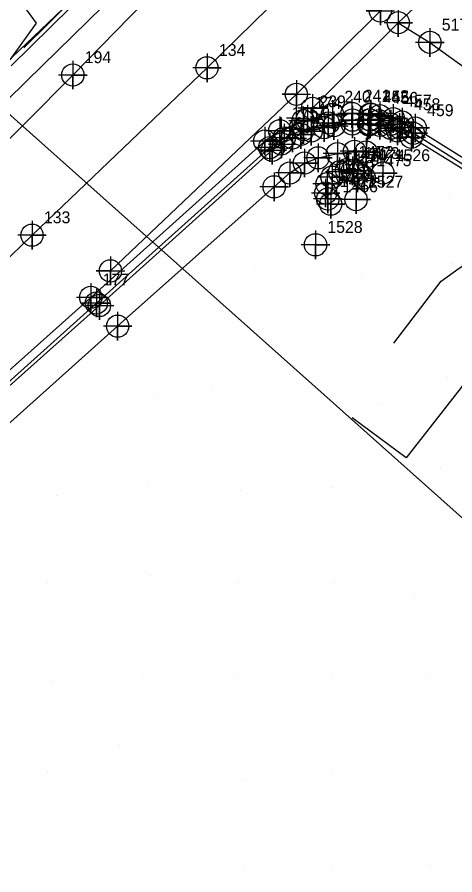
# Model space of a CAD drawing. Extents: x 1497074 to 1501343, y 481943 to 486114.
# Drawn here: x 1498357.2 to 1498449.4, y 484461 to 484641.5 of the extents above; entities that cross this region are included whole.
import ezdxf

# ---------------------------------------------------------------- set-up
doc = ezdxf.new("R2010")
doc.units = 0
for name, color, linetype in [('Exist Building Deck Patio Cogo Number', 7, 'Continuous'), ('Exist Building Deck Patio Cogo Point CELL', 7, 'Continuous'), ('Exist DTM Breakline', 7, 'Continuous'), ('Exist DTM Breakline Cogo Point CELL', 7, 'Continuous'), ('Exist DTM Crownline', 7, 'Continuous'), ('Exist DTM Crownline Cogo Number', 7, 'Continuous'), ('Exist DTM Crownline Cogo Point CELL', 7, 'Continuous'), ('Exist DTM Drainline', 7, 'Continuous'), ('Exist DTM Drainline Cogo Point CELL', 7, 'Continuous'), ('Exist DTM Regular Point CELL', 7, 'Continuous'), ('Exist DTM Regular Point Cogo Number', 7, 'Continuous'), ('Exist Guardrail', 7, 'Continuous'), ('Exist Roads Curbs', 7, 'Continuous'), ('Exist Roads Curbs Cogo Point CELL', 7, 'Continuous'), ('Exist Roads EOP', 7, 'Continuous'), ('Exist Roads EOP Cogo Number', 7, 'Continuous'), ('Exist Roads EOP Cogo Point CELL', 7, 'Continuous'), ('Exist Roads EOP Other', 7, 'Continuous'), ('Exist Roads EOP Other Cogo Point CELL', 7, 'Continuous'), ('Exist Roads EOT', 7, 'Continuous'), ('Exist Roads EOT Cogo Point CELL', 7, 'Continuous'), ('PH Exist DTM Boundary', 7, 'Continuous'), ('PH Exist DTM Breakline', 7, 'Continuous'), ('PH Exist DTM Obscure Area', 7, 'Continuous'), ('PH Exist DTM Point', 7, 'Continuous')]:
    doc.layers.add(name, color=color, linetype=linetype)

msp = doc.modelspace()

# ---------------------------------------------------------------- linework, layer by layer
at = {"layer": 'Exist Building Deck Patio Cogo Point CELL'}
for points in [[(1498425.08, 484611.93), (1498425.08, 484605.93), (1498425.08, 484608.93), (1498428.08, 484608.93), (1498422.08, 484608.93)], [(1498426.54, 484612.37), (1498426.54, 484606.37), (1498426.54, 484609.37), (1498429.54, 484609.37), (1498423.54, 484609.37)], [(1498427.76, 484612.14), (1498427.76, 484606.14), (1498427.76, 484609.14), (1498430.76, 484609.14), (1498424.76, 484609.14)], [(1498428.9, 484611.6), (1498428.9, 484605.6), (1498428.9, 484608.6), (1498431.9, 484608.6), (1498425.9, 484608.6)], [(1498422.44, 484609.42), (1498422.44, 484603.42), (1498422.44, 484606.42), (1498425.44, 484606.42), (1498419.44, 484606.42)], [(1498423.48, 484610.81), (1498423.48, 484604.81), (1498423.48, 484607.81), (1498426.48, 484607.81), (1498420.48, 484607.81)], [(1498430.28, 484610.62), (1498430.28, 484604.62), (1498430.28, 484607.62), (1498433.28, 484607.62), (1498427.28, 484607.62)], [(1498422.13, 484607.48), (1498422.13, 484601.48), (1498422.13, 484604.48), (1498425.13, 484604.48), (1498419.13, 484604.48)], [(1498422.59, 484606.22), (1498422.59, 484600.22), (1498422.59, 484603.22), (1498425.59, 484603.22), (1498419.59, 484603.22)], [(1498423.21, 484605.13), (1498423.21, 484599.13), (1498423.21, 484602.13), (1498426.21, 484602.13), (1498420.21, 484602.13)]]:
    msp.add_lwpolyline(points, dxfattribs=at)
for centre in [(1498425.08, 484608.93), (1498426.54, 484609.37), (1498427.76, 484609.14), (1498423.48, 484607.81), (1498428.9, 484608.6), (1498430.28, 484607.62), (1498422.44, 484606.42), (1498422.13, 484604.48), (1498422.59, 484603.22), (1498423.21, 484602.13)]:
    msp.add_circle(centre, 2.34, dxfattribs=at)
at = {"layer": 'Exist DTM Breakline'}
for points in [[(1498231.12, 484516.09), (1498254.57, 484537.6), (1498277.62, 484558.98), (1498300.74, 484581.31), (1498327.42, 484605.51), (1498348.5, 484625.92), (1498369.75, 484646.08), (1498390.54, 484667.65), (1498409.77, 484686.85)], [(1498467.53, 484668.57), (1498437.44, 484640.31), (1498419.38, 484622.3)]]:
    msp.add_lwpolyline(points, dxfattribs=at)
at = {"layer": 'Exist DTM Breakline Cogo Point CELL'}
for points in [[(1498437.44, 484643.31), (1498437.44, 484637.31), (1498437.44, 484640.31), (1498440.44, 484640.31), (1498434.44, 484640.31)], [(1498419.38, 484625.3), (1498419.38, 484619.3), (1498419.38, 484622.3), (1498422.38, 484622.3), (1498416.38, 484622.3)]]:
    msp.add_lwpolyline(points, dxfattribs=at)
for centre in [(1498437.44, 484640.31), (1498419.38, 484622.3)]:
    msp.add_circle(centre, 2.34, dxfattribs=at)
at = {"layer": 'Exist DTM Crownline'}
for points in [[(1498174.51, 484418.76), (1498211.76, 484454.63), (1498248.88, 484490.3), (1498287.28, 484525.89), (1498324.11, 484560.63), (1498360.29, 484595.61), (1498397.16, 484630.83), (1498419.58, 484652.79), (1498435.06, 484667.86), (1498471.56, 484703.24), (1498507.82, 484739.07), (1498544.95, 484775.1), (1498579.44, 484811.19), (1498593.31, 484825.81), (1498614.8, 484848.72), (1498648.9, 484888.1), (1498682.16, 484928.34), (1498714.31, 484969.37), (1498734.43, 484994.62)], [(1498437.44, 484640.31), (1498444.09, 484636.17), (1498465.05, 484621.1), (1498493.07, 484602.59), (1498534.57, 484574.94), (1498575.81, 484549.45), (1498620.08, 484521.62), (1498662.61, 484494.12)]]:
    msp.add_lwpolyline(points, dxfattribs=at)
at = {"layer": 'Exist DTM Crownline Cogo Point CELL'}
for points in [[(1498444.09, 484639.17), (1498444.09, 484633.17), (1498444.09, 484636.17), (1498447.09, 484636.17), (1498441.09, 484636.17)], [(1498397.16, 484633.83), (1498397.16, 484627.83), (1498397.16, 484630.83), (1498400.16, 484630.83), (1498394.16, 484630.83)], [(1498360.29, 484598.61), (1498360.29, 484592.61), (1498360.29, 484595.61), (1498363.29, 484595.61), (1498357.29, 484595.61)]]:
    msp.add_lwpolyline(points, dxfattribs=at)
for centre in [(1498444.09, 484636.17), (1498397.16, 484630.83), (1498360.29, 484595.61)]:
    msp.add_circle(centre, 2.34, dxfattribs=at)
at = {"layer": 'Exist DTM Drainline'}
for points in [[(1498187.75, 484405.46), (1498224.25, 484440.47), (1498261.49, 484476.23), (1498299.56, 484512.89), (1498328.14, 484540.34), (1498373.86, 484581.33), (1498410.37, 484614.04), (1498413.4, 484616.06), (1498417.45, 484617.85), (1498422.69, 484619.19), (1498427.8, 484619.82), (1498431.51, 484619.86)], [(1498456.84, 484606.28), (1498453.09, 484609.22), (1498440.58, 484617.04), (1498437.69, 484618.27), (1498435.85, 484618.97), (1498433.34, 484619.71), (1498431.51, 484619.86)]]:
    msp.add_lwpolyline(points, dxfattribs=at)
at = {"layer": 'Exist DTM Drainline Cogo Point CELL'}
for points in [[(1498422.69, 484622.19), (1498422.69, 484616.19), (1498422.69, 484619.19), (1498425.69, 484619.19), (1498419.69, 484619.19)], [(1498427.8, 484622.82), (1498427.8, 484616.82), (1498427.8, 484619.82), (1498430.8, 484619.82), (1498424.8, 484619.82)], [(1498431.4, 484622.92), (1498431.4, 484616.92), (1498431.4, 484619.92), (1498434.4, 484619.92), (1498428.4, 484619.92)], [(1498431.51, 484622.86), (1498431.51, 484616.86), (1498431.51, 484619.86), (1498434.51, 484619.86), (1498428.51, 484619.86)], [(1498433.34, 484622.71), (1498433.34, 484616.71), (1498433.34, 484619.71), (1498436.34, 484619.71), (1498430.34, 484619.71)], [(1498435.85, 484621.97), (1498435.85, 484615.97), (1498435.85, 484618.97), (1498438.85, 484618.97), (1498432.85, 484618.97)], [(1498417.45, 484620.85), (1498417.45, 484614.85), (1498417.45, 484617.85), (1498420.45, 484617.85), (1498414.45, 484617.85)], [(1498437.69, 484621.27), (1498437.69, 484615.27), (1498437.69, 484618.27), (1498440.69, 484618.27), (1498434.69, 484618.27)], [(1498413.4, 484619.06), (1498413.4, 484613.06), (1498413.4, 484616.06), (1498416.4, 484616.06), (1498410.4, 484616.06)], [(1498440.58, 484620.04), (1498440.58, 484614.04), (1498440.58, 484617.04), (1498443.58, 484617.04), (1498437.58, 484617.04)], [(1498410.37, 484617.04), (1498410.37, 484611.04), (1498410.37, 484614.04), (1498413.37, 484614.04), (1498407.37, 484614.04)], [(1498373.86, 484584.33), (1498373.86, 484578.33), (1498373.86, 484581.33), (1498376.86, 484581.33), (1498370.86, 484581.33)]]:
    msp.add_lwpolyline(points, dxfattribs=at)
for centre in [(1498427.8, 484619.82), (1498431.4, 484619.92), (1498431.51, 484619.86), (1498433.34, 484619.71), (1498417.45, 484617.85), (1498422.69, 484619.19), (1498435.85, 484618.97), (1498437.69, 484618.27), (1498413.4, 484616.06), (1498440.58, 484617.04), (1498410.37, 484614.04), (1498373.86, 484581.33)]:
    msp.add_circle(centre, 2.34, dxfattribs=at)
at = {"layer": 'Exist DTM Regular Point CELL'}
for points in [[(1498434.19, 484611.68), (1498434.19, 484605.68), (1498434.19, 484608.68), (1498437.19, 484608.68), (1498431.19, 484608.68)], [(1498428.55, 484606.1), (1498428.55, 484600.1), (1498428.55, 484603.1), (1498431.55, 484603.1), (1498425.55, 484603.1)], [(1498419.99, 484596.58), (1498419.99, 484590.58), (1498419.99, 484593.58), (1498422.99, 484593.58), (1498416.99, 484593.58)]]:
    msp.add_lwpolyline(points, dxfattribs=at)
for centre in [(1498434.19, 484608.68), (1498428.55, 484603.1), (1498419.99, 484593.58)]:
    msp.add_circle(centre, 2.34, dxfattribs=at)
at = {"layer": 'Exist Guardrail'}
msp.add_line((1498379.88, 484656.12), (1498358.55, 484635.05), dxfattribs=at)
at = {"layer": 'Exist Roads Curbs'}
for points in [[(1498431.18, 484618.93), (1498427.76, 484619.01), (1498423.87, 484618.64), (1498421.84, 484618.24), (1498419.09, 484617.51), (1498416.9, 484616.81), (1498415.13, 484616.04), (1498412.82, 484614.79), (1498410.87, 484613.46), (1498374.49, 484580.8), (1498343.01, 484552.74), (1498328.64, 484539.6), (1498300.15, 484512.34), (1498262.01, 484475.67), (1498224.83, 484439.99), (1498188.21, 484404.8)], [(1498431.18, 484618.93), (1498433.55, 484618.74), (1498435.81, 484618.12), (1498437.29, 484617.53), (1498440.2, 484616.21), (1498452.5, 484608.64), (1498456.49, 484605.77), (1498459.25, 484604.12), (1498463.26, 484601.65), (1498482.96, 484588.94), (1498524.52, 484561.81), (1498565.99, 484534.81), (1498608.43, 484507.17), (1498650.76, 484479.84)]]:
    msp.add_lwpolyline(points, dxfattribs=at)
at = {"layer": 'Exist Roads Curbs Cogo Point CELL'}
for points in [[(1498427.76, 484622.01), (1498427.76, 484616.01), (1498427.76, 484619.01), (1498425.03, 484619.01), (1498430.76, 484619.01)], [(1498431.48, 484622.01), (1498431.48, 484616.01), (1498431.48, 484619.01), (1498428.75, 484619.01), (1498434.48, 484619.01)], [(1498419.09, 484620.51), (1498419.09, 484614.51), (1498419.09, 484617.51), (1498416.36, 484617.51), (1498422.09, 484617.51)], [(1498421.84, 484621.24), (1498421.84, 484615.24), (1498421.84, 484618.24), (1498419.11, 484618.24), (1498424.84, 484618.24)], [(1498423.87, 484621.64), (1498423.87, 484615.64), (1498423.87, 484618.64), (1498421.14, 484618.64), (1498426.87, 484618.64)], [(1498431.18, 484621.93), (1498431.18, 484615.93), (1498431.18, 484618.93), (1498428.45, 484618.93), (1498434.18, 484618.93)], [(1498433.55, 484621.74), (1498433.55, 484615.74), (1498433.55, 484618.74), (1498430.82, 484618.74), (1498436.55, 484618.74)], [(1498435.81, 484621.12), (1498435.81, 484615.12), (1498435.81, 484618.12), (1498433.08, 484618.12), (1498438.81, 484618.12)], [(1498437.29, 484620.53), (1498437.29, 484614.53), (1498437.29, 484617.53), (1498434.56, 484617.53), (1498440.29, 484617.53)], [(1498415.13, 484619.04), (1498415.13, 484613.04), (1498415.13, 484616.04), (1498412.4, 484616.04), (1498418.13, 484616.04)], [(1498416.9, 484619.81), (1498416.9, 484613.81), (1498416.9, 484616.81), (1498414.17, 484616.81), (1498419.9, 484616.81)], [(1498440.2, 484619.21), (1498440.2, 484613.21), (1498440.2, 484616.21), (1498437.47, 484616.21), (1498443.2, 484616.21)], [(1498412.82, 484617.79), (1498412.82, 484611.79), (1498412.82, 484614.79), (1498410.09, 484614.79), (1498415.82, 484614.79)], [(1498410.87, 484616.46), (1498410.87, 484610.46), (1498410.87, 484613.46), (1498408.14, 484613.46), (1498413.87, 484613.46)], [(1498374.49, 484583.8), (1498374.49, 484577.8), (1498374.49, 484580.8), (1498371.76, 484580.8), (1498377.49, 484580.8)]]:
    msp.add_lwpolyline(points, dxfattribs=at)
for centre in [(1498421.84, 484618.24), (1498423.87, 484618.64), (1498427.76, 484619.01), (1498431.18, 484618.93), (1498431.48, 484619.01), (1498433.55, 484618.74), (1498435.81, 484618.12), (1498415.13, 484616.04), (1498416.9, 484616.81), (1498419.09, 484617.51), (1498437.29, 484617.53), (1498440.2, 484616.21), (1498412.82, 484614.79), (1498410.87, 484613.46), (1498374.49, 484580.8)]:
    msp.add_circle(centre, 2.34, dxfattribs=at)
at = {"layer": 'Exist Roads EOP'}
for points in [[(1498165.98, 484428.62), (1498180, 484442.69), (1498201.86, 484464.11), (1498239.3, 484499.9), (1498276.43, 484536.47), (1498313.13, 484573.18), (1498338.89, 484599.2), (1498349.09, 484609.46), (1498368.89, 484629.31), (1498383.9, 484644.63), (1498405.77, 484666.89), (1498429.88, 484691.21), (1498457.88, 484717.62), (1498496.23, 484753.16), (1498535.42, 484789.23), (1498556.84, 484809.01), (1498564.6, 484818.66), (1498566.38, 484823.54), (1498565.95, 484832.29), (1498567.61, 484834.53), (1498567.66, 484834.73)], [(1498418.31, 484620), (1498423.58, 484621), (1498427.67, 484621.2), (1498431.57, 484621.11)], [(1498431.57, 484621.11), (1498433.52, 484620.75), (1498436.39, 484620.14), (1498438.22, 484619.42), (1498441.01, 484618.16), (1498453.49, 484610.43), (1498457.85, 484607.96), (1498460.69, 484606.18), (1498464.61, 484603.11), (1498483.74, 484590.79), (1498525.81, 484563.47), (1498567.17, 484536.53), (1498609.6, 484508.85), (1498651.84, 484481.53)], [(1498417.39, 484619.69), (1498412.48, 484617.57), (1498409.32, 484615.42), (1498372.68, 484582.52), (1498341.5, 484554.69), (1498333.95, 484547.95), (1498326.84, 484541.45), (1498298.31, 484514.03), (1498263.32, 484480.54), (1498260.22, 484477.59), (1498223.09, 484441.85), (1498186.4, 484406.47)]]:
    msp.add_lwpolyline(points, dxfattribs=at)
at = {"layer": 'Exist Roads EOP Cogo Point CELL'}
for points in [[(1498368.89, 484632.31), (1498368.89, 484626.31), (1498368.89, 484629.31), (1498371.89, 484629.31), (1498365.89, 484629.31)], [(1498423.58, 484624), (1498423.58, 484618), (1498423.58, 484621), (1498426.58, 484621), (1498420.58, 484621)], [(1498427.67, 484624.2), (1498427.67, 484618.2), (1498427.67, 484621.2), (1498430.67, 484621.2), (1498424.67, 484621.2)], [(1498431.57, 484624.11), (1498431.57, 484618.11), (1498431.57, 484621.11), (1498434.57, 484621.11), (1498428.57, 484621.11)], [(1498431.67, 484624), (1498431.67, 484618), (1498431.67, 484621), (1498434.67, 484621), (1498428.67, 484621)], [(1498417.39, 484622.69), (1498417.39, 484616.69), (1498417.39, 484619.69), (1498420.39, 484619.69), (1498414.39, 484619.69)], [(1498418.31, 484623), (1498418.31, 484617), (1498418.31, 484620), (1498421.31, 484620), (1498415.31, 484620)], [(1498433.52, 484623.75), (1498433.52, 484617.75), (1498433.52, 484620.75), (1498436.52, 484620.75), (1498430.52, 484620.75)], [(1498436.39, 484623.14), (1498436.39, 484617.14), (1498436.39, 484620.14), (1498439.39, 484620.14), (1498433.39, 484620.14)], [(1498438.22, 484622.42), (1498438.22, 484616.42), (1498438.22, 484619.42), (1498441.22, 484619.42), (1498435.22, 484619.42)], [(1498412.48, 484620.57), (1498412.48, 484614.57), (1498412.48, 484617.57), (1498415.48, 484617.57), (1498409.48, 484617.57)], [(1498441.01, 484621.16), (1498441.01, 484615.16), (1498441.01, 484618.16), (1498444.01, 484618.16), (1498438.01, 484618.16)], [(1498409.32, 484618.42), (1498409.32, 484612.42), (1498409.32, 484615.42), (1498412.32, 484615.42), (1498406.32, 484615.42)], [(1498372.68, 484585.52), (1498372.68, 484579.52), (1498372.68, 484582.52), (1498375.68, 484582.52), (1498369.68, 484582.52)]]:
    msp.add_lwpolyline(points, dxfattribs=at)
for centre in [(1498368.89, 484629.31), (1498417.39, 484619.69), (1498418.31, 484620), (1498423.58, 484621), (1498427.67, 484621.2), (1498431.57, 484621.11), (1498431.67, 484621), (1498433.52, 484620.75), (1498436.39, 484620.14), (1498438.22, 484619.42), (1498441.01, 484618.16), (1498412.48, 484617.57), (1498409.32, 484615.42), (1498372.68, 484582.52)]:
    msp.add_circle(centre, 2.34, dxfattribs=at)
at = {"layer": 'Exist Roads EOP Other'}
msp.add_lwpolyline([(1498192.41, 484400.48), (1498228.96, 484435.67), (1498265.02, 484470.27), (1498304.15, 484507.96), (1498332.67, 484535.19), (1498346.87, 484548.32), (1498378.32, 484576.46), (1498411.29, 484605.77), (1498414.59, 484608.69), (1498417.68, 484610.78), (1498420.53, 484611.89), (1498424.6, 484612.76), (1498428.21, 484613.25), (1498430.66, 484613.09), (1498431.25, 484618.8)], dxfattribs=at)
at = {"layer": 'Exist Roads EOP Other Cogo Point CELL'}
for points in [[(1498431.25, 484621.8), (1498431.25, 484615.8), (1498431.25, 484618.8), (1498434.25, 484618.8), (1498428.25, 484618.8)], [(1498420.53, 484614.89), (1498420.53, 484608.89), (1498420.53, 484611.89), (1498423.53, 484611.89), (1498417.53, 484611.89)], [(1498424.6, 484615.76), (1498424.6, 484609.76), (1498424.6, 484612.76), (1498427.6, 484612.76), (1498421.6, 484612.76)], [(1498428.21, 484616.25), (1498428.21, 484610.25), (1498428.21, 484613.25), (1498431.21, 484613.25), (1498425.21, 484613.25)], [(1498430.66, 484616.09), (1498430.66, 484610.09), (1498430.66, 484613.09), (1498433.66, 484613.09), (1498427.66, 484613.09)], [(1498417.68, 484613.78), (1498417.68, 484607.78), (1498417.68, 484610.78), (1498420.68, 484610.78), (1498414.68, 484610.78)], [(1498414.59, 484611.69), (1498414.59, 484605.69), (1498414.59, 484608.69), (1498417.59, 484608.69), (1498411.59, 484608.69)], [(1498411.29, 484608.77), (1498411.29, 484602.77), (1498411.29, 484605.77), (1498414.29, 484605.77), (1498408.29, 484605.77)], [(1498378.32, 484579.46), (1498378.32, 484573.46), (1498378.32, 484576.46), (1498381.32, 484576.46), (1498375.32, 484576.46)]]:
    msp.add_lwpolyline(points, dxfattribs=at)
for centre in [(1498431.25, 484618.8), (1498424.6, 484612.76), (1498428.21, 484613.25), (1498430.66, 484613.09), (1498417.68, 484610.78), (1498420.53, 484611.89), (1498414.59, 484608.69), (1498411.29, 484605.77), (1498378.32, 484576.46)]:
    msp.add_circle(centre, 2.34, dxfattribs=at)
at = {"layer": 'Exist Roads EOT'}
msp.add_lwpolyline([(1498476.1, 484684.28), (1498463.39, 484672.07), (1498433.67, 484642.79), (1498415.98, 484625.26), (1498376.81, 484588.09)], dxfattribs=at)
at = {"layer": 'Exist Roads EOT Cogo Point CELL'}
for points in [[(1498433.67, 484645.79), (1498433.67, 484639.79), (1498433.67, 484642.79), (1498430.67, 484642.79), (1498436.67, 484642.79)], [(1498415.98, 484628.26), (1498415.98, 484622.26), (1498415.98, 484625.26), (1498412.98, 484625.26), (1498418.98, 484625.26)], [(1498376.81, 484591.09), (1498376.81, 484585.09), (1498376.81, 484588.09), (1498373.81, 484588.09), (1498379.81, 484588.09)]]:
    msp.add_lwpolyline(points, dxfattribs=at)
for centre in [(1498433.67, 484642.79), (1498415.98, 484625.26), (1498376.81, 484588.09)]:
    msp.add_circle(centre, 2.34, dxfattribs=at)
at = {"layer": 'PH Exist DTM Boundary'}
for points in [[(1498186.43, 484771.69), (1498560.82, 484438.23), (1498782.89, 484653.31), (1498924.23, 484841.06), (1498545.19, 485168.9), (1498406.94, 484985.26)], [(1497810.36, 484407.45), (1498181.14, 484070.49), (1498560.82, 484438.23), (1498186.43, 484771.69)]]:
    msp.add_lwpolyline(points, close=True, dxfattribs=at)
at = {"layer": 'PH Exist DTM Breakline'}
for points in [[(1498359.22, 484628.11), (1498384.86, 484653.26), (1498405.36, 484673.77), (1498430.29, 484697.78), (1498443.63, 484710.75), (1498464.77, 484731.29), (1498490.84, 484757.11), (1498497.71, 484764.47), (1498519.45, 484785.49), (1498553.87, 484820.26), (1498564.01, 484831.41), (1498565.79, 484832.49)], [(1498516.8, 484789.57), (1498514.61, 484786.75), (1498494.45, 484766.74), (1498466.99, 484739.94), (1498443.94, 484717.22), (1498412.06, 484686), (1498372.6, 484647.73), (1498355.93, 484631.24)], [(1498359.22, 484628.11), (1498332.83, 484602.19), (1498298.4, 484569.79), (1498260.92, 484534.8), (1498233.11, 484508.79), (1498204.33, 484482.06), (1498180.89, 484459.7), (1498151.91, 484432.44), (1498152.99, 484430.68), (1498155.59, 484428.47), (1498159.38, 484426.58), (1498162.81, 484425.97), (1498165.98, 484428.62)], [(1498436.52, 484572.85), (1498446.49, 484585.92), (1498450.23, 484588.64), (1498454.81, 484591.58), (1498458.06, 484594.29), (1498460.46, 484597.24), (1498462.65, 484601.96)], [(1498473.18, 484595.21), (1498471.77, 484594.13), (1498469.35, 484592.49), (1498463.5, 484583.68), (1498450.69, 484563.57), (1498439.11, 484548.76), (1498427.72, 484557.14)]]:
    msp.add_lwpolyline(points, dxfattribs=at)
at = {"layer": 'PH Exist DTM Obscure Area'}
msp.add_lwpolyline([(1498307.67, 484676.05), (1498312.8, 484681.46), (1498315.7, 484682.25), (1498320.76, 484680.6), (1498324.07, 484677.66), (1498326.55, 484670.45), (1498325.86, 484664.83), (1498325.1, 484660.14), (1498326.63, 484656.03), (1498331.08, 484651.8), (1498334.61, 484648.45), (1498338.49, 484645.41), (1498343.32, 484644.37), (1498348.86, 484644.88), (1498354.17, 484646.11), (1498358.72, 484643.58), (1498361.19, 484640.19), (1498355.63, 484632.52)], dxfattribs=at)
at = {"layer": 'PH Exist DTM Point'}
for p, q in [((1498409.2, 484603.84), (1498409.2, 484603.84)), ((1498448.2, 484603.67), (1498448.2, 484603.67)), ((1498448.61, 484589.57), (1498448.61, 484589.57)), ((1498407.1, 484589.08), (1498407.1, 484589.08)), ((1498429.75, 484587.15), (1498429.75, 484587.15)), ((1498447.77, 484565.58), (1498447.77, 484565.58)), ((1498398.23, 484563.14), (1498398.23, 484563.14)), ((1498386.18, 484562.18), (1498386.18, 484562.18)), ((1498433.37, 484559.88), (1498433.37, 484559.88)), ((1498446.38, 484546.52), (1498446.38, 484546.52)), ((1498384.83, 484543), (1498384.83, 484543)), ((1498423.61, 484542.6), (1498423.61, 484542.6)), ((1498443.61, 484542.6), (1498443.61, 484542.6)), ((1498365.47, 484540.83), (1498365.47, 484540.83)), ((1498404.27, 484541.97), (1498404.27, 484541.97)), ((1498384.96, 484524.01), (1498384.96, 484524.01)), ((1498363.61, 484522.6), (1498363.61, 484522.6)), ((1498403.61, 484522.6), (1498403.61, 484522.6)), ((1498423.93, 484522.3), (1498423.93, 484522.3)), ((1498440.95, 484519.84), (1498440.95, 484519.84)), ((1498364.59, 484501.67), (1498364.59, 484501.67)), ((1498383.63, 484502.58), (1498383.63, 484502.58)), ((1498403.61, 484502.6), (1498403.61, 484502.6)), ((1498423.61, 484502.6), (1498423.61, 484502.6)), ((1498444.02, 484502.57), (1498444.02, 484502.57)), ((1498378.67, 484488.31), (1498378.67, 484488.31)), ((1498363.61, 484482.6), (1498363.61, 484482.6)), ((1498423.61, 484482.6), (1498423.61, 484482.6)), ((1498405.17, 484481.12), (1498405.17, 484481.12)), ((1498404.8, 484462.19), (1498404.8, 484462.19)), ((1498423.61, 484462.6), (1498423.61, 484462.6)), ((1498444.05, 484463.05), (1498444.05, 484463.05))]:
    msp.add_line(p, q, dxfattribs=at)

# ---------------------------------------------------------------- texts
at = {"layer": 'Exist Building Deck Patio Cogo Number'}
for s, p in [('1471', (1498427.58, 484611.43)), ('1472', (1498429.04, 484611.87)), ('1473', (1498430.26, 484611.64)), ('1474', (1498431.4, 484611.1)), ('1469', (1498424.94, 484608.92)), ('1470', (1498425.98, 484610.31)), ('1475', (1498432.78, 484610.12)), ('1468', (1498424.63, 484606.98)), ('1467', (1498425.09, 484605.72)), ('1466', (1498425.71, 484604.63))]:
    msp.add_text(s, height=2.5, dxfattribs=at).set_placement(p)
at = {"layer": 'Exist DTM Crownline Cogo Number'}
for s, p in [('517', (1498446.59, 484638.67)), ('134', (1498399.66, 484633.33)), ('133', (1498362.79, 484598.11))]:
    msp.add_text(s, height=2.5, dxfattribs=at).set_placement(p)
at = {"layer": 'Exist DTM Regular Point Cogo Number'}
for s, p in [('1526', (1498436.69, 484611.18)), ('1527', (1498431.05, 484605.6)), ('1528', (1498422.49, 484596.08))]:
    msp.add_text(s, height=2.5, dxfattribs=at).set_placement(p)
at = {"layer": 'Exist Roads EOP Cogo Number'}
for s, p in [('194', (1498371.39, 484631.81)), ('240', (1498426.08, 484623.5)), ('241', (1498430.17, 484623.7)), ('242', (1498434.07, 484623.61)), ('455', (1498434.17, 484623.5)), ('456', (1498436.02, 484623.25)), ('174', (1498419.89, 484622.19)), ('239', (1498420.81, 484622.5)), ('457', (1498438.89, 484622.64)), ('458', (1498440.72, 484621.92)), ('175', (1498414.98, 484620.07)), ('459', (1498443.51, 484620.66)), ('176', (1498411.82, 484617.92)), ('177', (1498375.18, 484585.02))]:
    msp.add_text(s, height=2.5, dxfattribs=at).set_placement(p)

doc.saveas('drawing.dxf')
